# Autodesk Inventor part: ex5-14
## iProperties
Shininess: 64.0
Length Units: 11272
Angle Units: 11279
Time Units: 11290
Mass Units: 11286
Length Display Precision: 3
Angle Display Precision: 2
Compacted: True
Part Number: ex5-14
Document SubType Name: Modeling
Created: 2003-11
Designer: Elise Moss
Cost Center: 0 lbmass
Authority: 0.49 in^3
Manufacturer: Standard
Standards Organization: Custom
Density: 0.0
Volumn: 0.0
Area: 0.0
PropertySet Name: Model Information
Control State: 0
Master: False
Checked Out: False
SaveDate: 2003-11-14
SaveTime: 20:48
TotalMass: 0 lbmass
TotalVolume: 0.49 in^3
Author: Elise Moss
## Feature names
1. Revolution1
2. Shell1
3. Split1
